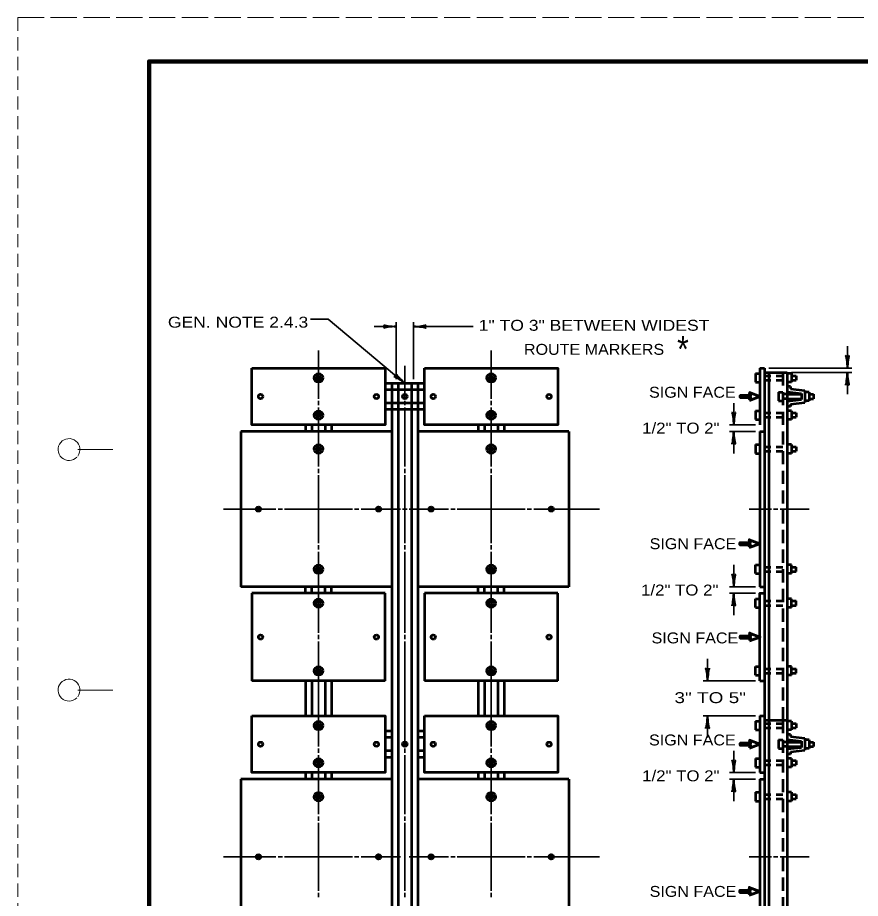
# Model space of a CAD drawing. Extents: x -45 to 635, y -382 to 59.
# Drawn here: x -44.9 to 147.9, y -142.8 to 58.5 of the extents above; entities that cross this region are included whole.
import ezdxf
from ezdxf.enums import TextEntityAlignment as Align

# ---------------------------------------------------------------- set-up
doc = ezdxf.new("R2010")
doc.units = 0
for name, pattern in [('LONG_DASHED', [7.5, 6, -1.5]), ('MEDIUM_DASHED', [4.5, 3, -1.5]), ('SHORT_DASHED', [2.7, 1.5, -1.2])]:
    doc.linetypes.add(name, pattern=pattern)
doc.layers.add('1', color=7, linetype='Continuous', lineweight=53)
doc.layers.add('61', color=7, linetype='Continuous', lineweight=35)

msp = doc.modelspace()

# ---------------------------------------------------------------- linework, layer by layer
at = {"layer": '1', "linetype": 'MEDIUM_DASHED', "lineweight": 13}
msp.add_line((-44.831, 58.54), (-44.891, -381.5), dxfattribs=at)
at = {"layer": '1', "lineweight": 35}
for p, q in [((41.687, -24.09), (41.687, -11.09)), ((45.687, -24.09), (45.687, -11.09)), ((36.687, -12.09), (41.687, -12.09)), ((45.687, -12.09), (59.29, -12.09)), ((23.937, -17.59), (23.937, -28.59)), ((63.437, -17.59), (63.437, -28.59)), ((144.922, -21.59), (144.922, -16.59)), ((43.687, -21.09), (43.687, -28.59)), ((126.922, -21.59), (145.922, -21.59)), ((132.172, -22.59), (145.922, -22.59)), ((144.922, -27.59), (144.922, -22.59)), ((23.937, -29.09), (23.937, -30.09)), ((43.687, -29.09), (43.687, -30.09)), ((63.437, -29.09), (63.437, -30.09)), ((118.922, -34.59), (118.922, -29.59)), ((23.937, -30.59), (23.937, -44.09)), ((43.687, -30.59), (43.687, -44.09)), ((63.437, -30.59), (63.437, -44.09)), ((123.922, -34.59), (117.922, -34.59)), ((123.922, -36.09), (117.922, -36.09)), ((118.922, -41.09), (118.922, -36.09)), ((23.937, -44.59), (23.937, -45.59)), ((23.937, -46.09), (23.937, -61.59)), ((43.687, -44.59), (43.687, -45.59)), ((43.687, -46.09), (43.687, -61.59)), ((63.437, -44.59), (63.437, -45.59)), ((63.437, -46.09), (63.437, -61.59)), ((2.187, -53.84), (14.187, -53.84)), ((14.687, -53.84), (15.687, -53.84)), ((16.187, -53.84), (31.687, -53.84)), ((32.187, -53.84), (33.187, -53.84)), ((43.187, -53.84), (44.187, -53.84)), ((44.687, -53.84), (45.687, -53.84)), ((45.687, -53.84), (53.687, -53.84)), ((54.187, -53.84), (55.187, -53.84)), ((55.687, -53.84), (71.187, -53.84)), ((71.687, -53.84), (72.687, -53.84)), ((73.187, -53.84), (88.187, -53.84)), ((122.422, -53.84), (127.547, -53.84)), ((128.047, -53.84), (129.047, -53.84)), ((129.547, -53.84), (136.172, -53.84)), ((23.937, -62.09), (23.937, -63.09)), ((43.687, -62.09), (43.687, -63.09)), ((63.437, -62.09), (63.437, -63.09)), ((23.937, -63.59), (23.937, -82.09)), ((43.687, -63.59), (43.687, -82.09)), ((63.437, -63.59), (63.437, -82.09)), ((118.922, -71.59), (118.922, -66.59)), ((123.922, -71.59), (117.922, -71.59)), ((123.922, -73.09), (117.922, -73.09)), ((118.922, -78.09), (118.922, -73.09)), ((23.937, -82.59), (23.937, -83.59)), ((23.937, -84.09), (23.937, -97.09)), ((43.687, -82.59), (43.687, -83.59)), ((43.687, -84.09), (43.687, -108.09)), ((63.437, -82.59), (63.437, -83.59)), ((63.437, -84.09), (63.437, -97.09)), ((112.922, -93.09), (112.922, -88.09)), ((123.922, -93.09), (111.922, -93.09)), ((23.937, -97.09), (23.937, -108.09)), ((63.437, -97.09), (63.437, -108.09)), ((123.922, -101.09), (111.922, -101.09)), ((112.922, -106.09), (112.922, -101.09)), ((23.937, -108.59), (23.937, -109.59)), ((43.687, -108.59), (43.687, -109.59)), ((63.437, -108.59), (63.437, -109.59)), ((23.937, -110.09), (23.937, -123.59)), ((43.687, -110.09), (43.687, -123.59)), ((63.437, -110.09), (63.437, -123.59)), ((118.922, -114.09), (118.922, -109.09)), ((123.922, -114.09), (117.922, -114.09)), ((123.922, -115.59), (117.922, -115.59)), ((118.922, -120.59), (118.922, -115.59)), ((23.937, -124.09), (23.937, -125.09)), ((43.687, -124.09), (43.687, -125.09)), ((63.437, -124.09), (63.437, -125.09)), ((23.937, -125.59), (23.937, -141.09)), ((43.687, -125.59), (43.687, -141.09)), ((63.437, -125.59), (63.437, -141.09)), ((2.187, -133.34), (14.187, -133.34)), ((14.687, -133.34), (15.687, -133.34)), ((16.187, -133.34), (31.687, -133.34)), ((32.187, -133.34), (33.187, -133.34)), ((33.687, -133.34), (41.687, -133.34)), ((41.687, -133.34), (42.687, -133.34)), ((44.687, -133.34), (45.687, -133.34)), ((45.687, -133.34), (53.687, -133.34)), ((46.806, -133.34), (48.687, -133.34)), ((54.187, -133.34), (55.187, -133.34)), ((55.687, -133.34), (71.187, -133.34)), ((71.687, -133.34), (72.687, -133.34)), ((73.187, -133.34), (88.187, -133.34)), ((122.422, -133.34), (127.547, -133.34)), ((128.047, -133.34), (129.047, -133.34)), ((129.547, -133.34), (136.172, -133.34)), ((23.937, -141.59), (23.937, -142.59)), ((43.687, -141.59), (43.687, -142.59)), ((63.437, -141.59), (63.437, -142.59))]:
    msp.add_line(p, q, dxfattribs=at)
at = {"layer": '1'}
for p, q in [((124.922, -21.59), (124.922, -34.59)), ((124.922, -21.59), (125.922, -21.59)), ((125.922, -21.59), (125.922, -36.09)), ((123.922, -22.84), (123.922, -24.84)), ((123.922, -22.84), (124.922, -22.84)), ((125.922, -22.59), (131.172, -22.59)), ((126.922, -22.59), (126.922, -102.09)), ((131.172, -22.59), (131.172, -102.09)), ((132.172, -22.84), (131.172, -22.84)), ((132.172, -22.84), (132.172, -24.84)), ((132.172, -23.34), (133.172, -23.34)), ((133.172, -23.34), (133.172, -24.34)), ((48.187, -25.09), (39.187, -25.09)), ((40.687, -25.09), (40.687, -115.59)), ((42.187, -25.09), (42.187, -115.59)), ((45.187, -25.09), (45.187, -115.59)), ((46.687, -25.09), (46.687, -115.59)), ((123.922, -24.84), (124.922, -24.84)), ((132.172, -24.84), (131.172, -24.84)), ((131.922, -25.84), (131.172, -25.84)), ((131.922, -25.84), (131.922, -26.34)), ((132.172, -24.34), (133.172, -24.34)), ((48.187, -26.59), (39.187, -26.59)), ((129.172, -27.09), (129.172, -29.09)), ((129.172, -27.09), (130.172, -27.09)), ((131.172, -27.011), (134.422, -27.372)), ((131.172, -27.59), (134.422, -27.59)), ((131.922, -26.34), (135.172, -26.701)), ((134.422, -27.372), (134.422, -28.807)), ((135.172, -26.701), (135.172, -29.479)), ((136.172, -27.09), (135.172, -27.09)), ((136.172, -27.09), (136.172, -29.09)), ((136.172, -27.59), (137.172, -27.59)), ((137.172, -27.59), (137.172, -28.59)), ((48.187, -29.59), (39.187, -29.59)), ((129.172, -29.09), (130.172, -29.09)), ((131.172, -28.59), (134.422, -28.59)), ((131.172, -29.169), (134.422, -28.807)), ((131.922, -29.84), (135.172, -29.479)), ((131.922, -29.84), (131.922, -30.34)), ((136.172, -29.09), (135.172, -29.09)), ((136.172, -28.59), (137.172, -28.59)), ((48.187, -31.09), (39.187, -31.09)), ((123.922, -31.34), (123.922, -33.34)), ((123.922, -31.34), (124.922, -31.34)), ((131.922, -30.34), (131.172, -30.34)), ((132.172, -31.34), (131.172, -31.34)), ((132.172, -31.34), (132.172, -33.34)), ((132.172, -31.84), (133.172, -31.84)), ((133.172, -31.84), (133.172, -32.84)), ((123.922, -33.34), (124.922, -33.34)), ((132.172, -33.34), (131.172, -33.34)), ((132.172, -32.84), (133.172, -32.84)), ((40.687, -36.09), (6.187, -36.09)), ((6.187, -36.09), (6.187, -71.59)), ((20.937, -34.59), (20.937, -36.09)), ((22.437, -34.59), (22.437, -36.09)), ((25.437, -34.59), (25.437, -36.09)), ((26.937, -34.59), (26.937, -36.09)), ((81.187, -36.09), (46.687, -36.09)), ((60.437, -34.59), (60.437, -36.09)), ((61.937, -34.59), (61.937, -36.09)), ((64.937, -34.59), (64.937, -36.09)), ((66.437, -34.59), (66.437, -36.09)), ((81.187, -36.09), (81.187, -71.59)), ((124.922, -36.09), (124.922, -71.59)), ((124.922, -36.09), (125.922, -36.09)), ((125.922, -36.09), (125.922, -101.09)), ((123.922, -39.09), (123.922, -41.09)), ((123.922, -39.09), (124.922, -39.09)), ((132.172, -39.09), (131.172, -39.09)), ((132.172, -39.09), (132.172, -41.09)), ((132.172, -39.59), (133.172, -39.59)), ((133.172, -39.59), (133.172, -40.59)), ((123.922, -41.09), (124.922, -41.09)), ((132.172, -41.09), (131.172, -41.09)), ((132.172, -40.59), (133.172, -40.59)), ((123.922, -68.59), (123.922, -66.59)), ((123.922, -66.59), (124.922, -66.59)), ((132.172, -66.59), (131.172, -66.59)), ((132.172, -68.59), (132.172, -66.59)), ((132.172, -67.09), (133.172, -67.09)), ((132.172, -68.09), (133.172, -68.09)), ((133.172, -68.09), (133.172, -67.09)), ((123.922, -68.59), (124.922, -68.59)), ((132.172, -68.59), (131.172, -68.59)), ((40.687, -71.59), (6.187, -71.59)), ((20.937, -73.09), (20.937, -71.59)), ((22.437, -73.09), (22.437, -71.59)), ((25.437, -73.09), (25.437, -71.59)), ((26.937, -73.09), (26.937, -71.59)), ((81.187, -71.59), (46.687, -71.59)), ((60.437, -73.09), (60.437, -71.59)), ((61.937, -73.09), (61.937, -71.59)), ((64.937, -73.09), (64.937, -71.59)), ((66.437, -73.09), (66.437, -71.59)), ((124.922, -71.59), (125.922, -71.59)), ((8.687, -73.09), (8.687, -93.09)), ((39.187, -73.09), (8.687, -73.09)), ((39.187, -93.09), (39.187, -73.09)), ((78.687, -73.09), (48.187, -73.09)), ((48.187, -73.09), (48.187, -93.09)), ((78.687, -93.09), (78.687, -73.09)), ((123.922, -76.34), (123.922, -74.34)), ((123.922, -74.34), (124.922, -74.34)), ((132.172, -74.34), (131.172, -74.34)), ((132.172, -76.34), (132.172, -74.34)), ((123.922, -76.34), (124.922, -76.34)), ((132.172, -76.34), (131.172, -76.34)), ((132.172, -74.84), (133.172, -74.84)), ((132.172, -75.84), (133.172, -75.84)), ((133.172, -75.84), (133.172, -74.84)), ((123.922, -91.84), (123.922, -89.84)), ((123.922, -89.84), (124.922, -89.84)), ((132.172, -89.84), (131.172, -89.84)), ((132.172, -91.84), (132.172, -89.84)), ((132.172, -90.34), (133.172, -90.34)), ((133.172, -91.34), (133.172, -90.34)), ((123.922, -91.84), (124.922, -91.84)), ((132.172, -91.84), (131.172, -91.84)), ((132.172, -91.34), (133.172, -91.34)), ((39.187, -93.09), (8.687, -93.09)), ((20.937, -93.09), (20.937, -101.09)), ((22.437, -93.09), (22.437, -101.09)), ((25.437, -93.09), (25.437, -101.09)), ((26.937, -93.09), (26.937, -101.09)), ((78.687, -93.09), (48.187, -93.09)), ((60.437, -93.09), (60.437, -101.09)), ((61.937, -93.09), (61.937, -101.09)), ((64.937, -93.09), (64.937, -101.09)), ((66.437, -93.09), (66.437, -101.09)), ((124.922, -93.09), (125.922, -93.09)), ((123.922, -102.34), (123.922, -104.34)), ((123.922, -102.34), (124.922, -102.34)), ((124.922, -101.09), (124.922, -114.09)), ((124.922, -101.09), (125.922, -101.09)), ((125.922, -102.09), (131.172, -102.09)), ((126.922, -102.09), (126.922, -181.59)), ((131.172, -102.09), (131.172, -181.59)), ((132.172, -102.34), (131.172, -102.34)), ((132.172, -102.34), (132.172, -104.34)), ((40.687, -104.59), (39.187, -104.59)), ((48.187, -104.59), (46.687, -104.59)), ((123.922, -104.34), (124.922, -104.34)), ((132.172, -104.34), (131.172, -104.34)), ((132.172, -102.84), (133.172, -102.84)), ((132.172, -103.84), (133.172, -103.84)), ((133.172, -102.84), (133.172, -103.84)), ((40.687, -106.09), (39.187, -106.09)), ((48.187, -106.09), (46.687, -106.09)), ((129.172, -106.59), (129.172, -108.59)), ((129.172, -106.59), (130.172, -106.59)), ((131.922, -105.34), (131.172, -105.34)), ((131.172, -106.511), (134.422, -106.872)), ((131.922, -105.34), (131.922, -105.84)), ((131.922, -105.84), (135.172, -106.201)), ((135.172, -106.201), (135.172, -108.979)), ((136.172, -106.59), (135.172, -106.59)), ((136.172, -106.59), (136.172, -108.59)), ((129.172, -108.59), (130.172, -108.59)), ((131.172, -107.09), (134.422, -107.09)), ((131.172, -108.09), (134.422, -108.09)), ((131.172, -108.669), (134.422, -108.307)), ((134.422, -106.872), (134.422, -108.307)), ((136.172, -108.59), (135.172, -108.59)), ((136.172, -107.09), (137.172, -107.09)), ((136.172, -108.09), (137.172, -108.09)), ((137.172, -107.09), (137.172, -108.09)), ((40.687, -109.09), (39.187, -109.09)), ((40.687, -110.59), (39.187, -110.59)), ((48.187, -109.09), (46.687, -109.09)), ((48.187, -110.59), (46.687, -110.59)), ((131.922, -109.84), (131.172, -109.84)), ((131.922, -109.34), (135.172, -108.979)), ((131.922, -109.34), (131.922, -109.84)), ((123.922, -110.84), (123.922, -112.84)), ((123.922, -110.84), (124.922, -110.84)), ((132.172, -110.84), (131.172, -110.84)), ((132.172, -110.84), (132.172, -112.84)), ((132.172, -111.34), (133.172, -111.34)), ((132.172, -112.34), (133.172, -112.34)), ((133.172, -111.34), (133.172, -112.34)), ((20.937, -114.09), (20.937, -115.59)), ((22.437, -114.09), (22.437, -115.59)), ((25.437, -114.09), (25.437, -115.59)), ((26.937, -114.09), (26.937, -115.59)), ((60.437, -114.09), (60.437, -115.59)), ((61.937, -114.09), (61.937, -115.59)), ((64.937, -114.09), (64.937, -115.59)), ((66.437, -114.09), (66.437, -115.59)), ((123.922, -112.84), (124.922, -112.84)), ((124.922, -114.09), (125.922, -114.09)), ((132.172, -112.84), (131.172, -112.84)), ((40.687, -115.59), (6.187, -115.59)), ((6.187, -115.59), (6.187, -151.09)), ((40.687, -115.59), (40.687, -151.09)), ((42.187, -115.59), (42.187, -151.09)), ((45.187, -115.59), (45.187, -151.09)), ((81.187, -115.59), (46.687, -115.59)), ((46.687, -115.59), (46.687, -151.09)), ((81.187, -115.59), (81.187, -151.09)), ((124.922, -115.59), (124.922, -151.09)), ((124.922, -115.59), (125.922, -115.59)), ((123.922, -118.59), (123.922, -120.59)), ((123.922, -118.59), (124.922, -118.59)), ((132.172, -118.59), (131.172, -118.59)), ((132.172, -118.59), (132.172, -120.59)), ((123.922, -120.59), (124.922, -120.59)), ((132.172, -120.59), (131.172, -120.59)), ((132.172, -119.09), (133.172, -119.09)), ((132.172, -120.09), (133.172, -120.09)), ((133.172, -119.09), (133.172, -120.09))]:
    msp.add_line(p, q, dxfattribs=at)
at = {"layer": '1', "linetype": 'SHORT_DASHED'}
for p, q in [((125.922, -23.34), (131.172, -23.34)), ((125.922, -24.34), (131.172, -24.34)), ((131.172, -27.59), (130.172, -27.59)), ((131.172, -28.59), (130.172, -28.59)), ((125.922, -31.84), (131.172, -31.84)), ((125.922, -32.84), (131.172, -32.84)), ((125.922, -39.59), (131.172, -39.59)), ((125.922, -40.59), (131.172, -40.59)), ((125.922, -67.09), (131.172, -67.09)), ((125.922, -68.09), (131.172, -68.09)), ((125.922, -74.84), (131.172, -74.84)), ((125.922, -75.84), (131.172, -75.84)), ((125.922, -90.34), (131.172, -90.34)), ((125.922, -91.34), (131.172, -91.34)), ((125.922, -102.84), (131.172, -102.84)), ((125.922, -103.84), (131.172, -103.84)), ((131.172, -107.09), (130.172, -107.09)), ((131.172, -108.09), (130.172, -108.09)), ((125.922, -111.34), (131.172, -111.34)), ((125.922, -112.34), (131.172, -112.34)), ((125.922, -119.09), (131.172, -119.09)), ((125.922, -120.09), (131.172, -120.09))]:
    msp.add_line(p, q, dxfattribs=at)
at = {"layer": '1', "linetype": 'MEDIUM_DASHED'}
for p, q in [((130.172, -22.59), (130.172, -102.09)), ((130.172, -102.09), (130.172, -181.59))]:
    msp.add_line(p, q, dxfattribs=at)
at = {"layer": '1', "lineweight": 35}
for points in [[(43.687, -25.09), (26.17, -10.419), (22.101, -10.419)], [(33.687, -53.84), (41.687, -53.84), (42.687, -53.84)]]:
    msp.add_lwpolyline(points, dxfattribs=at)
at = {"layer": '1'}
for points in [[(8.687, -21.59), (39.187, -21.59), (39.187, -34.59), (8.687, -34.59)], [(48.187, -21.59), (78.687, -21.59), (78.687, -34.59), (48.187, -34.59)], [(8.687, -101.09), (39.187, -101.09), (39.187, -114.09), (8.687, -114.09)], [(48.187, -101.09), (78.687, -101.09), (78.687, -114.09), (48.187, -114.09)]]:
    msp.add_lwpolyline(points, close=True, dxfattribs=at)
at = {"layer": '1', "lineweight": 60}
for points in [[(122.537, -28.99), (124.922, -28.09), (122.537, -27.19), (122.807, -27.865), (120.422, -27.865), (120.422, -28.315), (122.807, -28.315)], [(122.469, -62.642), (124.854, -61.741), (122.469, -60.841), (122.739, -61.517), (120.354, -61.517), (120.354, -61.966), (122.739, -61.966)], [(122.537, -83.99), (124.922, -83.09), (122.537, -82.19), (122.807, -82.865), (120.422, -82.865), (120.422, -83.315), (122.807, -83.315)], [(122.537, -108.49), (124.922, -107.59), (122.537, -106.69), (122.807, -107.365), (120.422, -107.365), (120.422, -107.815), (122.807, -107.815)], [(122.469, -142.142), (124.854, -141.242), (122.469, -140.341), (122.739, -141.017), (120.354, -141.017), (120.354, -141.466), (122.739, -141.466)]]:
    msp.add_lwpolyline(points, close=True, dxfattribs=at)
at = {"layer": '1'}
for points in [[(124.922, -93.09), (124.922, -73.09), (125.922, -73.09)], [(125.922, -101.09), (125.922, -115.59), (125.922, -180.59)]]:
    msp.add_lwpolyline(points, dxfattribs=at)
for centre, radius in [((23.937, -23.84), 1), ((23.937, -23.84), 0.5), ((63.437, -23.84), 1), ((63.437, -23.84), 0.5), ((10.687, -28.09), 0.5), ((37.187, -28.09), 0.5), ((43.687, -28.09), 0.5), ((50.187, -28.09), 0.5), ((76.687, -28.09), 0.5), ((23.937, -32.34), 1), ((23.937, -32.34), 0.5), ((63.437, -32.34), 1), ((63.437, -32.34), 0.5), ((23.937, -40.09), 1), ((23.937, -40.09), 0.5), ((63.437, -40.09), 1), ((63.437, -40.09), 0.5), ((10.187, -53.84), 0.5), ((37.687, -53.84), 0.5), ((49.687, -53.84), 0.5), ((77.187, -53.84), 0.5), ((23.937, -67.59), 1), ((23.937, -67.59), 0.5), ((63.437, -67.59), 1), ((63.437, -67.59), 0.5), ((23.937, -75.34), 1), ((63.437, -75.34), 1), ((23.937, -75.34), 0.5), ((63.437, -75.34), 0.5), ((10.687, -83.09), 0.5), ((37.187, -83.09), 0.5), ((50.187, -83.09), 0.5), ((76.687, -83.09), 0.5), ((23.937, -90.84), 1), ((23.937, -90.84), 0.5), ((63.437, -90.84), 1), ((63.437, -90.84), 0.5), ((23.937, -103.34), 1), ((63.437, -103.34), 1), ((23.937, -103.34), 0.5), ((63.437, -103.34), 0.5), ((10.687, -107.59), 0.5), ((37.187, -107.59), 0.5), ((43.687, -107.59), 0.5), ((50.187, -107.59), 0.5), ((76.687, -107.59), 0.5), ((23.937, -111.84), 1), ((23.937, -111.84), 0.5), ((63.437, -111.84), 1), ((63.437, -111.84), 0.5), ((23.937, -119.59), 1), ((63.437, -119.59), 1), ((23.937, -119.59), 0.5), ((63.437, -119.59), 0.5), ((10.187, -133.34), 0.5), ((37.687, -133.34), 0.5), ((49.687, -133.34), 0.5), ((77.187, -133.34), 0.5)]:
    msp.add_circle(centre, radius, dxfattribs=at)
at = {"layer": '1', "lineweight": 40}
for centre, major_axis, ratio, start_param, end_param in [((40.566, -11.878), (1.756, -0.176), 0.07063, 3.1407148, 5.41811), ((40.566, -11.878), (1.756, -0.176), 0.07063, 3.1407148, 5.41811), ((46.778, -11.813), (-1.786, -0.156), 0.122415, 0.8963533, 3.1415927), ((40.596, -12.366), (1.786, 0.156), 0.122415, 0.8963533, 3.1415927), ((40.596, -12.366), (1.786, 0.156), 0.122415, 0.8963533, 3.1415927), ((46.808, -12.301), (-1.756, 0.176), 0.07063, 3.1407148, 5.41811), ((144.646, -20.499), (0.156, -1.786), 0.122415, 0.8963533, 3.1415927), ((144.646, -20.499), (0.156, -1.786), 0.122415, 0.8963533, 3.1415927), ((145.134, -20.469), (-0.176, -1.756), 0.07063, 3.1407148, 5.41811), ((145.134, -20.469), (-0.176, -1.756), 0.07063, 3.1407148, 5.41811), ((42.673, -24.601), (1.469, -1.027), 0.122415, 0.8963533, 3.1415927), ((42.964, -24.208), (1.234, -1.262), 0.07063, 3.1407148, 5.41811), ((144.71, -23.71), (0.176, 1.756), 0.07063, 3.1407148, 5.41811), ((145.198, -23.681), (-0.156, 1.786), 0.122415, 0.8963533, 3.1415927), ((118.646, -33.499), (0.156, -1.786), 0.122415, 0.8963533, 3.1415927), ((118.646, -33.499), (0.156, -1.786), 0.122415, 0.8963533, 3.1415927), ((119.134, -33.469), (-0.176, -1.756), 0.07063, 3.1407148, 5.41811), ((119.134, -33.469), (-0.176, -1.756), 0.07063, 3.1407148, 5.41811), ((118.71, -37.21), (0.176, 1.756), 0.07063, 3.1407148, 5.41811), ((119.198, -37.181), (-0.156, 1.786), 0.122415, 0.8963533, 3.1415927), ((118.646, -70.499), (0.156, -1.786), 0.122415, 0.8963533, 3.1415927), ((118.646, -70.499), (0.156, -1.786), 0.122415, 0.8963533, 3.1415927), ((119.134, -70.469), (-0.176, -1.756), 0.07063, 3.1407148, 5.41811), ((119.134, -70.469), (-0.176, -1.756), 0.07063, 3.1407148, 5.41811), ((118.71, -74.21), (0.176, 1.756), 0.07063, 3.1407148, 5.41811), ((119.198, -74.181), (-0.156, 1.786), 0.122415, 0.8963533, 3.1415927), ((112.646, -91.999), (0.156, -1.786), 0.122415, 0.8963533, 3.1415927), ((112.646, -91.999), (0.156, -1.786), 0.122415, 0.8963533, 3.1415927), ((113.134, -91.969), (-0.176, -1.756), 0.07063, 3.1407148, 5.41811), ((113.134, -91.969), (-0.176, -1.756), 0.07063, 3.1407148, 5.41811), ((112.71, -102.21), (0.176, 1.756), 0.07063, 3.1407148, 5.41811), ((112.71, -102.21), (0.176, 1.756), 0.07063, 3.1407148, 5.41811), ((113.198, -102.181), (-0.156, 1.786), 0.122415, 0.8963533, 3.1415927), ((113.198, -102.181), (-0.156, 1.786), 0.122415, 0.8963533, 3.1415927), ((118.646, -112.999), (0.156, -1.786), 0.122415, 0.8963533, 3.1415927), ((118.646, -112.999), (0.156, -1.786), 0.122415, 0.8963533, 3.1415927), ((119.134, -112.969), (-0.176, -1.756), 0.07063, 3.1407148, 5.41811), ((119.134, -112.969), (-0.176, -1.756), 0.07063, 3.1407148, 5.41811), ((118.71, -116.71), (0.176, 1.756), 0.07063, 3.1407148, 5.41811), ((119.198, -116.681), (-0.156, 1.786), 0.122415, 0.8963533, 3.1415927)]:
    msp.add_ellipse(centre, major_axis=major_axis, ratio=ratio, start_param=start_param, end_param=end_param, dxfattribs=at)
at = {"layer": '61', "linetype": 'LONG_DASHED', "lineweight": 13}
msp.add_line((-44.831, 58.54), (635.189, 58.54), dxfattribs=at)
at = {"layer": '61', "lineweight": 13}
for p, q in [((-31.111, -40.22), (-23.131, -40.2)), ((-31.131, -95.22), (-23.131, -95.22))]:
    msp.add_line(p, q, dxfattribs=at)
at = {"layer": '61', "lineweight": 158}
msp.add_lwpolyline([(624.209, 48.54), (-14.831, 48.54), (-14.831, -371.48)], dxfattribs=at)
at = {"layer": '61', "lineweight": 13}
for centre, end in [((-33.133, -40.219), 316.23216), ((-33.133, -95.219), 315.37577)]:
    msp.add_arc(centre, 2.5, 323.13009, end, dxfattribs=at)

# ---------------------------------------------------------------- texts
at = {"layer": '1'}
for s, height, width, p in [('GEN. NOTE 2.4.3', 2.5, 1.2, (5.536, -12.345)), ('1" TO 3" BETWEEN WIDEST', 2.5, 1.2, (86.976, -13.061)), ('ROUTE MARKERS', 2.5, 1.1, (86.976, -18.561)), ('*', 6, 0.85, (107.301, -20.24)), ('SIGN FACE', 2.5, 1.1, (109.459, -28.37)), ('1/2" TO 2"', 2.5, 1.15, (106.822, -36.566)), ('SIGN FACE', 2.5, 1.1, (109.601, -62.998)), ('1/2" TO 2"', 2.5, 1.15, (106.568, -73.593)), ('SIGN FACE', 2.5, 1.1, (110.041, -84.539)), ('3" TO 5"', 2.5, 1.3, (113.54, -98.194)), ('SIGN FACE', 2.5, 1.1, (109.459, -107.87)), ('1/2" TO 2"', 2.5, 1.15, (106.822, -116.066)), ('SIGN FACE', 2.5, 1.1, (109.601, -142.498))]:
    msp.add_text(s, height=height, dxfattribs=dict(at, width=width)).set_placement(p, align=Align.CENTER)

doc.saveas('drawing.dxf')
